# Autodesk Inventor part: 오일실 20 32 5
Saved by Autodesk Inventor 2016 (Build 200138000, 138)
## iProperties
Created: 2024-08
Part Number: 오일실 20 32 5
Material: 일반
Description: 오일 실 - 비스프링, 조립 GA
Document SubType Name: Modeling
Designer: pc-2
Density: 1 g/cm^3
Appearance: 기본값
Author: jhkim
Sending System: Autodesk Inventor 2025
Preprocessor: ST-DEVELOPER v20
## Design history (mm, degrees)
node "오일실 20 32 51"
node "솔리드1"
body "Solid1"
